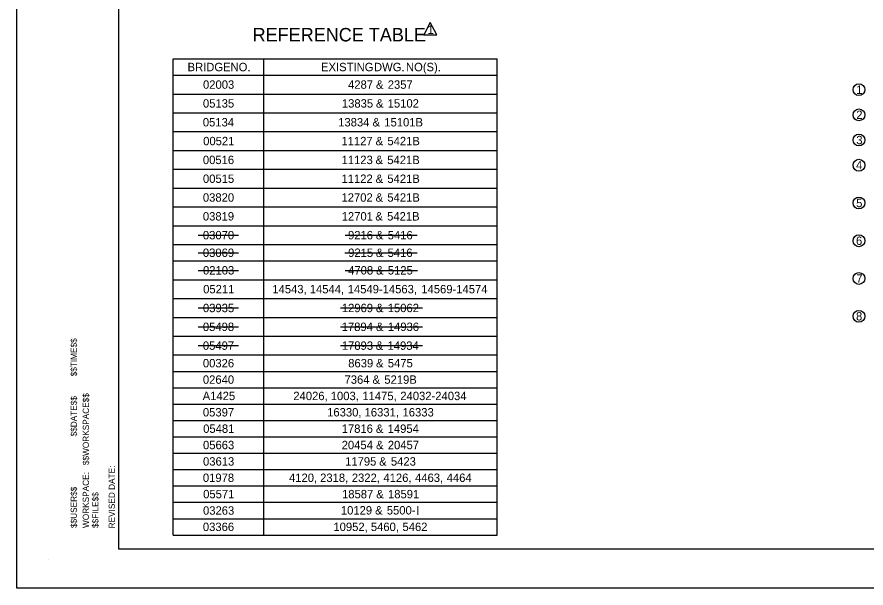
# Model space of a CAD drawing. Extents: x 18 to 14744716, y -5 to 1829144.
# Drawn here: x 17.78 to 30.4, y -5.37 to 3.12 of the extents above; entities that cross this region are included whole.
import ezdxf

# ---------------------------------------------------------------- set-up
doc = ezdxf.new("R2010")
doc.units = 0
for name, color, linetype in [('B_Dimensions', 7, 'Continuous'), ('B_Text', 7, 'Continuous'), ('B_Title Text', 7, 'Continuous'), ('R_Border', 7, 'Continuous'), ('R_No Plot', 7, 'Continuous')]:
    doc.layers.add(name, color=color, linetype=linetype)

msp = doc.modelspace()

# ---------------------------------------------------------------- linework, layer by layer
at = {"layer": 'B_Dimensions'}
for p, q in [((23.918, 3.039), (23.822, 2.855)), ((24.015, 2.855), (23.918, 3.039)), ((23.822, 2.855), (24.015, 2.855)), ((20.471, -0.125), (21.071, -0.125)), ((22.653, -0.125), (23.726, -0.125)), ((20.471, -0.386), (21.071, -0.386)), ((22.652, -0.386), (23.725, -0.386)), ((20.471, -0.648), (21.071, -0.648)), ((22.655, -0.648), (23.728, -0.648)), ((20.471, -1.208), (21.071, -1.208)), ((22.585, -1.208), (23.806, -1.208)), ((20.471, -1.488), (21.071, -1.488)), ((22.585, -1.488), (23.806, -1.488)), ((20.471, -1.767), (21.071, -1.767)), ((22.585, -1.767), (23.806, -1.767))]:
    msp.add_line(p, q, dxfattribs=at)
for centre in [(30.291, 2.039), (30.291, 1.664), (30.291, 1.29), (30.291, 0.915), (30.291, 0.354), (30.291, -0.208), (30.291, -0.769), (30.291, -1.331)]:
    msp.add_circle(centre, 0.0881, dxfattribs=at)
at = {"layer": 'B_Text'}
for p, q in [((20.096, 2.497), (24.914, 2.497)), ((20.096, -4.584), (20.096, 2.497)), ((21.446, -4.584), (21.446, 2.497)), ((24.914, -4.584), (24.914, 2.497)), ((20.096, 2.254), (24.914, 2.254)), ((20.096, 1.974), (24.914, 1.974)), ((20.096, 1.694), (24.914, 1.694)), ((20.096, 1.415), (24.914, 1.415)), ((20.096, 1.135), (24.914, 1.135)), ((20.096, 0.855), (24.914, 0.855)), ((20.096, 0.575), (24.914, 0.575)), ((20.096, 0.295), (24.914, 0.295)), ((20.096, 0.015), (24.914, 0.015)), ((20.096, -0.265), (24.914, -0.265)), ((20.096, -0.508), (24.914, -0.508)), ((20.096, -0.788), (24.914, -0.788)), ((20.096, -1.068), (24.914, -1.068)), ((20.096, -1.348), (24.914, -1.348)), ((20.096, -1.627), (24.914, -1.627)), ((20.096, -1.907), (24.914, -1.907)), ((20.096, -2.151), (24.914, -2.151)), ((20.096, -2.394), (24.914, -2.394)), ((20.096, -2.637), (24.914, -2.637)), ((20.096, -2.881), (24.914, -2.881)), ((20.096, -3.124), (24.914, -3.124)), ((20.096, -3.367), (24.914, -3.367)), ((20.096, -3.611), (24.914, -3.611)), ((20.096, -3.854), (24.914, -3.854)), ((20.096, -4.098), (24.914, -4.098)), ((20.096, -4.341), (24.914, -4.341)), ((20.096, -4.584), (24.914, -4.584))]:
    msp.add_line(p, q, dxfattribs=at)
at = {"layer": 'B_Title Text'}
msp.add_line((20.096, 2.497), (20.096, 2.497), dxfattribs=at)
at = {"layer": 'R_Border'}
for p, q in [((19.293, -4.796), (19.293, 16.051)), ((51.2, -4.796), (19.293, -4.796)), ((18.245, -4.945), (18.245, -4.945))]:
    msp.add_line(p, q, dxfattribs=at)
at = {"layer": 'R_No Plot'}
msp.add_lwpolyline([(17.777, 16.628), (51.777, 16.628), (51.777, -5.372), (17.777, -5.372)], close=True, dxfattribs=at)

# ---------------------------------------------------------------- texts
at = {"layer": 'B_Text'}
for s, height, p in [('1', 0.125, (23.878, 2.869)), ('BRIDGE', 0.1248, (20.312, 2.313)), (' NO.', 0.1248, (20.905, 2.313)), ('EXISTING', 0.1248, (22.296, 2.313)), (' DWG.', 0.1248, (23.037, 2.313)), (' NO(S).', 0.1248, (23.512, 2.313)), ('02003', 0.1248, (20.542, 2.052)), ('4287', 0.1248, (22.698, 2.052)), (' &', 0.1248, (23.066, 2.052)), (' 2357', 0.1248, (23.241, 2.052)), ('1', 0.125, (30.251, 1.976)), ('05135', 0.1248, (20.541, 1.772)), ('13835', 0.1248, (22.606, 1.772)), (' &', 0.1248, (23.066, 1.772)), (' 15102', 0.1248, (23.24, 1.772)), ('2', 0.125, (30.251, 1.602)), ('05134', 0.1248, (20.539, 1.492)), ('13834', 0.1248, (22.551, 1.492)), (' &', 0.1248, (23.015, 1.492)), (' 15101B', 0.1248, (23.19, 1.492)), ('00521', 0.1248, (20.544, 1.212)), ('11127', 0.1248, (22.599, 1.212)), (' &', 0.1248, (23.061, 1.212)), (' 5421B', 0.1248, (23.236, 1.212)), ('3', 0.125, (30.251, 1.227)), ('00516', 0.1248, (20.54, 0.932)), ('11123', 0.1248, (22.601, 0.932)), (' &', 0.1248, (23.06, 0.932)), (' 5421B', 0.1248, (23.234, 0.932)), ('4', 0.125, (30.246, 0.853)), ('00515', 0.1248, (20.541, 0.652)), ('11122', 0.1248, (22.6, 0.652)), (' &', 0.1248, (23.061, 0.652)), (' 5421B', 0.1248, (23.235, 0.652)), ('03820', 0.1248, (20.54, 0.373)), ('12702', 0.1248, (22.6, 0.373)), (' &', 0.1248, (23.061, 0.373)), (' 5421B', 0.1248, (23.235, 0.373)), ('5', 0.125, (30.249, 0.291)), ('03819', 0.1248, (20.54, 0.093)), ('12701', 0.1248, (22.603, 0.093)), (' &', 0.1248, (23.057, 0.093)), (' 5421B', 0.1248, (23.232, 0.093)), ('03070', 0.1248, (20.54, -0.187)), ('9216', 0.1248, (22.697, -0.187)), (' &', 0.1248, (23.066, -0.187)), (' 5416', 0.1248, (23.241, -0.187)), ('6', 0.125, (30.247, -0.27)), ('03069', 0.1248, (20.54, -0.449)), ('9215', 0.1248, (22.699, -0.449)), (' &', 0.1248, (23.065, -0.449)), (' 5416', 0.1248, (23.239, -0.449)), ('02103', 0.1248, (20.542, -0.71)), ('4708', 0.1248, (22.699, -0.71)), (' &', 0.1248, (23.068, -0.71)), (' 5125', 0.1248, (23.242, -0.71)), ('7', 0.125, (30.251, -0.832)), ('05211', 0.1248, (20.544, -0.99)), ('14543,', 0.1248, (21.572, -0.99)), (' 14544,', 0.1248, (22.082, -0.99)), (' 14549-14563,', 0.1248, (22.646, -0.99)), (' 14569-14574', 0.1248, (23.74, -0.99)), ('03935', 0.1248, (20.541, -1.27)), ('12969', 0.1248, (22.605, -1.27)), (' &', 0.1248, (23.066, -1.27)), (' 15062', 0.1248, (23.241, -1.27)), ('8', 0.125, (30.247, -1.393)), ('05498', 0.1248, (20.54, -1.55)), ('17894', 0.1248, (22.603, -1.55)), (' &', 0.1248, (23.067, -1.55)), (' 14936', 0.1248, (23.242, -1.55)), ('05497', 0.1248, (20.54, -1.83)), ('17893', 0.1248, (22.605, -1.83)), (' &', 0.1248, (23.063, -1.83)), (' 14934', 0.1248, (23.238, -1.83)), ('00326', 0.1248, (20.54, -2.091)), ('8639', 0.1248, (22.7, -2.091)), (' &', 0.1248, (23.067, -2.091)), (' 5475', 0.1248, (23.242, -2.091)), ('02640', 0.1248, (20.54, -2.335)), ('7364', 0.1248, (22.645, -2.335)), (' &', 0.1248, (23.015, -2.335)), (' 5219B', 0.1248, (23.19, -2.335)), ('A1425', 0.1248, (20.537, -2.578)), ('24026,', 0.1248, (21.884, -2.578)), (' 1003,', 0.1248, (22.394, -2.578)), (' 11475,', 0.1248, (22.864, -2.578)), (' 24032-24034', 0.1248, (23.428, -2.578)), ('05397', 0.1248, (20.54, -2.821)), ('16330,', 0.1248, (22.387, -2.821)), (' 16331,', 0.1248, (22.897, -2.821)), (' 16333', 0.1248, (23.461, -2.821)), ('05481', 0.1248, (20.544, -3.065)), ('17816', 0.1248, (22.603, -3.065)), (' &', 0.1248, (23.065, -3.065)), (' 14954', 0.1248, (23.24, -3.065)), ('05663', 0.1248, (20.542, -3.308)), ('20454', 0.1248, (22.603, -3.308)), (' &', 0.1248, (23.067, -3.308)), (' 20457', 0.1248, (23.242, -3.308)), ('03613', 0.1248, (20.542, -3.552)), ('11795', 0.1248, (22.654, -3.552)), (' &', 0.1248, (23.113, -3.552)), (' 5423', 0.1248, (23.288, -3.552)), ('01978', 0.1248, (20.54, -3.795)), ('4120,', 0.1248, (21.82, -3.795)), (' 2318,', 0.1248, (22.236, -3.795)), (' 2322,', 0.1248, (22.707, -3.795)), (' 4126,', 0.1248, (23.177, -3.795)), (' 4463,', 0.1248, (23.647, -3.795)), (' 4464', 0.1248, (24.117, -3.795)), ('05571', 0.1248, (20.544, -4.038)), ('18587', 0.1248, (22.608, -4.038)), (' 18591', 0.1248, (23.245, -4.038)), (' &', 0.1248, (23.07, -4.038)), ('03263', 0.1248, (20.542, -4.282)), ('10129', 0.1248, (22.591, -4.279)), (' &', 0.1248, (23.053, -4.279)), (' 5500-', 0.1248, (23.227, -4.279)), ('I', 0.131, (23.71, -4.285)), ('03366', 0.1248, (20.54, -4.525)), ('10952,', 0.1248, (22.48, -4.525)), (' 5460,', 0.1248, (22.99, -4.525)), (' 5462', 0.1248, (23.46, -4.525))]:
    msp.add_text(s, height=height, dxfattribs=at).set_placement(p)
at = {"layer": 'B_Title Text'}
msp.add_text('REFERENCE TABLE', height=0.2004, dxfattribs=at).set_placement((21.279, 2.756))
at = {"layer": 'R_Border'}
for s, p in [('$$TIME$$', (18.667, -2.225)), ('$$DATE$$', (18.667, -3.118)), ('$$WORKSPACE$$', (18.846, -3.545)), ('WORKSPACE:', (18.846, -4.48)), ('REVISED DATE:', (19.232, -4.486)), ('$$USER$$', (18.667, -4.48)), ('$$FILE$$', (18.988, -4.48))]:
    msp.add_text(s, height=0.0918, rotation=90, dxfattribs=at).set_placement(p)

doc.saveas('drawing.dxf')
